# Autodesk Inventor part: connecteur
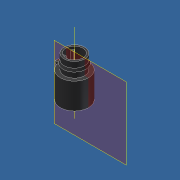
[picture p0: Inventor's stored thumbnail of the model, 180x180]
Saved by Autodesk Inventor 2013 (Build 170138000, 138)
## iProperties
Created: 2011-10
Part Number: connecteur
Material: Caoutchouc
Document SubType Name: Modeling
Designer: Laur
Mass: 0.383555 g
Surface Area: 3.08002 cm^2
Volume: 0.412425 cm^3
Density: 0.93 g/cm^3
Author: Laur
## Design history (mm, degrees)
sketch "Esquisse1"
  geometry: A1 r 4.3 centre (4.814, 0.4) between (0.544, -0.1) and (0.544, 0.9) reference; A2 r 4.3 centre (4.814, 0.4) between (0.544, 0.9) and (0.544, -0.1); 1 further point
  constraints: 2 point on circle, 1 centre point, 1 coincident
  node "Référence4"
node "Plan de construction1"
node "Plan de construction3"
extrude "grande base cyl" new body sketch "Esquisse1" stored distance "d0" = 10; taper "d1" = 0 deg
sketch "Esquisse2"
  geometry: L1 (-5.327, -0.5)-(-4.271, -0.5) reference; L2 (-4.271, 0.5)-(-5.327, 0.5) reference; L3 (-4.271, 0.5)-(-5.327, 0.5); L4 (-4.271, -0.5)-(-5.327, -0.5); C1 r 4.3 at (0, 0) reference; A1 r 5.35 centre (0, 0) between (-5.327, 0.5) and (-5.327, -0.5) reference; A2 r 4.3 centre (0, 0) between (-4.271, -0.5) and (-4.271, 0.5) reference; A3 r 4.3 centre (0, 0) between (-4.271, 0.5) and (-4.271, -0.5)
  constraints: 4 end point, 2 point on circle, 1 centre point, 1 coincident, 1 parallel
extrude "téton d'orientation" join sketch "Esquisse2" distance "d2" = 0.8; taper "d3" = 0 deg
node "Plan de construction2"
  node "Axe de construction1"
sketch "Esquisse3"
  geometry: L1 (-0.8, 5.327)-(-0.8, 5.327); L2 (-1.951, 5.81)-(-0.8, 5.327); L3 (-0.8, 4.271)-(-1.951, 5.81); L4 (-0.8, 5.327)-(-0.8, 4.271); L5 (-10.313, -4.296)-(0.786, -4.296); L6 (-1.951, -4.296)-(-8.728, -4.296); L7 (6.3, 2.6)-(10.7, 2.6); L8 (10.7, 2.6)-(10.7, 3.15); L9 (10.7, 3.15)-(6.3, 3.15); L10 (8.924, 3.15)-(8.1, 3.45); L11 (8.1, 3.45)-(8.1, 3.15); L12 (5.69, 0)-(11.512, 0); L13 (-14.678, 0)-(15.877, 0) reference; L14 (6.3, 2.6)-(6.3, 3.15); L15 (6.3, 2.6)-(6.3, 3.15); L16 (6.3, 4.3)-(6.3, -4.271) reference
  constraints: 28 end point, 4 point on line, 2 collinear, 2 perpendicular, 1 horizontal, 1 parallel
  dimensions: "d20" = 0.3 distance from line of L10.end L9; "d21" = 2.6 distance between parallel lines of L11 L8; "d22" = 160 deg angle of L10 L9; "d24" = 5.2 diameter of L7 L12; "d25" = 6.3 diameter of L9 L12; "d26" = 4.4 distance between parallel lines of L14 L8
revolve "clip male" sketch "Esquisse3" stored, may be unused: angle "d11" = 90 deg
sketch "Esquisse4"
  geometry: L1 (-1.428, 1.096)-(-1.765, 1.909); L2 (-1.765, 1.909)-(-2.301, 1.211); L3 (-2.301, 1.211)-(-1.428, 1.096); L4 (-1.428, -1.096)-(-2.301, -1.211); L5 (-2.301, -1.211)-(-1.765, -1.909); L6 (0, 0)-(-3.401, -2.61); L7 (0, 0)-(-4.099, 3.145); L8 (0, 0)-(-6.289, 0); L9 (-1.428, -1.096)-(-1.765, -1.909); A1 r 2.6 centre (0, 0) between (-1.765, 1.909) and (-2.301, 1.211)
  constraints: 18 end point, 4 point on circle, 2 point on line, 1 centre point, 3 other
  dimensions: "d12" = 75 deg angle of L6 L7; "d13" = 1.8 distance of L6.start L1.start; "d14" = 1.8 distance of L4.start L6.start (= d13); "d15" = 60 deg angle of L9 L4 (= d18); "d18" = 60 deg angle of L3 L1
extrude "Ergots détrompeurs" join sketch "Esquisse4" distance "d16" = 3.5; taper "d17" = 0 deg
node "Solide1"
node "Corps solides"
node "Corps surfaciques"
node "Référence7"
node "Référence8"
node "Boucle projetée4"
node "Référence9"
other parameters: "d19" = 0
